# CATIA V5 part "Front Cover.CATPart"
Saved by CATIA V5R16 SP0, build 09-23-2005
Part number: Cover
Bounding box of the stored display mesh (mm): x -44 to 44, y 0 to 16, z -43.985 to 43.985
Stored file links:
  C:\V5_education\CATIA Data\ASD\Power Transmission Gear Assembly\Assembly Data\Front Cover.CATPart
  C:\V5_education\CATIA Data\ASD\Power Transmission Gear Assembly\Assembly Data\Power Transmission Gear Assembly.CATProduct
  C:\V5_education\CATIA Data\ASD\Power Transmission Gear Assembly\Assembly Data\Power Transmission Gear.CATPart
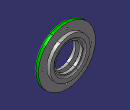
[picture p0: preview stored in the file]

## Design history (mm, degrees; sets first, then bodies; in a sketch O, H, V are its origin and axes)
Set1
  DatumSurface1: linked copy from another document
Set2 "Reference Data"
  Point1 "Center Point": (0, 0, 0)
Body1 (main body)
  Sketch1 on yz-plane, origin (0, 0, 0), H (0, 1, 0), V (0, 0, 1)
    line L1 (0, 0) -> (0, 31)
    line L2 (0, 31) -> (4, 31)
    line L3 (4, 31) -> (4, 44)
    line L4 (4, 44) -> (11, 44)
    line L5 (11, 44) -> (11, 31)
    line L6 (11, 31) -> (16, 31)
    line L7 (16, 31) -> (16, 0)
    point P7 (16, 0)
    axis line L8 (0, 0) -> (16, 0)
    distance L8 L2 = 31
    distance L8 L4 = 44
    distance L1 L7 = 16
    distance L5 L3 = 7
    distance L5 L7 = 5
    distance L6 H = 31
    vertical: L1 V, L3 V, L5 V, L7 V
    horizontal: L2 H, L4 H, L6 H, L8 H
    coincidence: P7 H
  Shaft1: profile Sketch1, axis Sketch1.L8, angle 360
  Body2
    Sketch2 on yz-plane, origin (0, 0, 0), H (0, 1, 0), V (0, 0, 1)
      point P1 (0, 20.5)
      line L1 (0, 20.5) -> (4.2019, 20.5)
      line L2 (4.2019, 20.5) -> (5, 27)
      point P3 (5, 27)
      line L3 (5, 27) -> (9, 27)
      point P4 (9, 27)
      line L4 (9, 27) -> (9.7981, 20.5)
      point P5 (9.7981, 20.5)
      line L5 (9.7981, 20.5) -> (14, 20.5)
      line L6 (14, 20.5) -> (14, 25.3)
      line L7 (14, 25.3) -> (17, 25.3)
      line L8 (17, 25.3) -> (17, 0)
      point P9 (17, 0)
      line L9 (0, 20.5) -> (0, 0)
      axis line L10 (0, 0) -> (17, 0)
      construction line L11 (7, 27) -> (7, 0)
      point P10 (7, 27)
      point P11 (7, 0)
      distance L3 H = 27
      distance L1 H = 20.5
      angle L2 L4 = 14
      distance L11 L8 = 10
      distance L8 L9 = 17
      distance L7 H = 25.3
      distance L6 L8 = 3
      distance P4 P3 = 4
      coincidence: P1 V, P5 L1, P9 H, P11 L10
      horizontal: L1 H, L3 H, L5 H, L7 H, L10 H
      vertical: L6 V, L8 V, L9 V, L11 V
      midpoint: P10 L3
      symmetry: P3 P4 L11, L2 L4 L11
    Shaft2: profile Sketch2, axis Sketch2.L10, angle 360
    Fillet1: radius 3, on edge [face of Shaft2 from Sketch2.L6 | face of Shaft2 from Sketch2.L7]
  Remove1: tool Body2
  Fillet2: radius 3, on edge [face of Shaft1 from Sketch1.L3 | face of Shaft1 from Sketch1.L4]
  Fillet3: radius 3, on edge [face of Shaft1 from Sketch1.L1 | face of Shaft1 from Sketch1.L2]
  Fillet4: radius 3, on edge [face of Shaft1 from Sketch1.L2 | face of Shaft1 from Sketch1.L3]
  Body3
    Sketch3 on face of Shaft1 from Sketch1.L3, origin (-9.4665, 4, 27.9071), H (1, 0, 0), V (0, 0, 1)
      point P1 (9.4665, 9.0929)
      reference intersected line E1 through (0, -27.9071) direction (-1, 0) from xy-plane
      reference intersected line E2 through (9.4665, 0) direction (0, 1) from yz-plane
      distance P1 E1 = 37
      coincidence: E2 P1
    Hole1: placed by Sketch3, at (0, 4, 37) direction (0, 1, 0), diameter 3.242, depth 10, counterbore diameter 6, counterbore depth 4.4, threaded "M4", thread diameter 4, thread depth 5.6, pitch 0.7
    CircPattern1: of the body so far, instances 4, angular step 90 {= 360.0*1 deg/CircPattern1.AngularNumber}, axis from face of Shaft1 from Sketch1.L4
  Assemble1: tool Body3
  AssyPrtSPLIT1: SplitPlane DatumSurface1, _MechModInactiveResultOUT result of AssyPrtSPLIT1, deactivated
